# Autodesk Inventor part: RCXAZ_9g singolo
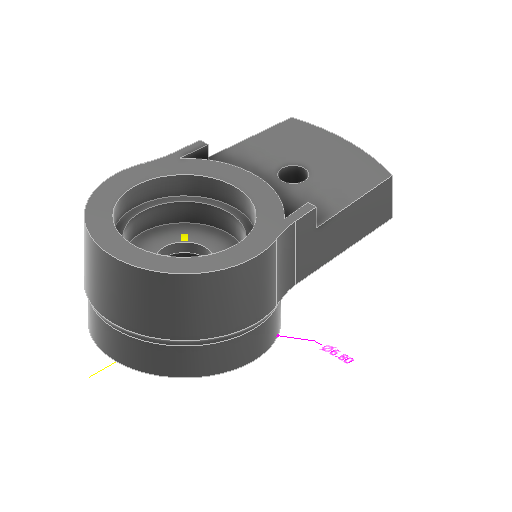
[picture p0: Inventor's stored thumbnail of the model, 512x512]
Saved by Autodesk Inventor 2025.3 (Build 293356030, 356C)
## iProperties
Created: 2026-03
Part Number: RCXAZ_9g singolo
Material: Generico
Document SubType Name: Modeling
Designer: R5800u
Density: 1 g/cm^3
Appearance: Liscia - Nero
Author: R5800u
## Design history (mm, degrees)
node "Annotazioni"
  node "Quota diametro 4" dims "d44" = 6.8 (derived)
sketch "Schizzo1"
  geometry: C1 r 3.4 at (0, 0); 1 further point
  constraints: 1 centre point, 1 coincident
  dimensions: "d0" = 6.8 diameter of C1
extrude "Estrusione1" new body sketch "Schizzo1" distance "d1" = 4; taper "d2" = 0 deg
sketch "Schizzo2" dims "d4" = 4
  geometry: L1 (0, 0)-(0, 15.5); L2 (-3.398, 0.127)-(-1.992, 15.68); L3 (0, 0)-(-8.473, 0); L4 (0, 0)-(0, -18); L5 (-3.398, -0.127)-(-3.398, 0.127); L6 (3.398, -0.127)-(3.398, 0.127); L7 (3.398, 0.127)-(1.992, 15.68); L8 (-3.386, -0.307)-(-1.767, -18.16); L9 (3.476, 0.685)-(1.767, -18.16); C1 r 3.4 at (0, 0); A1 r 3.4 centre (0, 0) between (-3.398, -0.127) and (-3.398, 0.127) reference; A2 r 1.774 centre (0, -18) between (-1.767, -18.16) and (1.767, -18.16); 11 further points
  constraints: 18 end point, 4 point on circle, 3 coincident, 3 symmetric about line, 3 tangent, 2 centre point, 2 vertical, 1 horizontal, 7 other
  dimensions: "d3" = 15.5 distance of L1.start L1.end; "d57" = 18 distance of L1.start L4.end
extrude "Estrusione2" join sketch "Schizzo2" distance "d5" = 2; taper "d6" = 0 deg
sketch "Schizzo3"
  geometry: C1 r 2.75 at (0, 0); A1 r 3.4 centre (0, 0) between (3.365, 0.485) and (-3.365, 0.485) reference; A2 r 3.4 centre (0, 0) between (3.365, 0.485) and (-3.365, 0.485) reference; A3 r 3.4 centre (0, 0) between (-3.365, 0.485) and (3.365, 0.485); 10 further points
  constraints: 2 centre point, 2 coincident, 1 point on circle
  dimensions: "d7" = 5.5 diameter of C1
extrude "Estrusione3" join sketch "Schizzo3" distance "d8" = 0.01; taper "d9" = 0 deg
sketch "Schizzo5"
  geometry: C1 r 2.75 at (0, 0) reference; 2 further points
  constraints: 1 coincident
hole "Foro1" sketch "Schizzo5" at (0, 0) diameter "d10" = 2.2; stored, may be unused: countersink angle "d14" = 90 deg, drill point angle "d16" = 118 deg; dims "d11" = 6, "d12" = 4.75, "d13" = 1, "d15" = 8
sketch "Schizzo6"
  geometry: C1 r 2.5 at (0, 0); 1 further point
  constraints: 1 centre point, 1 coincident
  dimensions: "d17" = 5 diameter of C1
extrude "Estrusione4" cut sketch "Schizzo6" distance "d18" = 2.5; taper "d19" = 0 deg
sketch "Schizzo7"
  geometry: L1 (-3.386, -0.309)-(-2, -15.5) reference; L2 (1.992, -15.681)-(3.386, -0.307) reference; A1 r 3.4 centre (0, 0) between (-3.386, -0.309) and (3.386, -0.307) reference; A2 r 2 centre (0, -15.5) between (-2, -15.5) and (1.992, -15.681) reference; 2 further points
  constraints: 1 coincident
hole "Foro2" sketch "Schizzo7" at (0, -15.5) diameter "d20" = 1.2; stored, may be unused: countersink angle "d24" = 90 deg, drill point angle "d26" = 118 deg; dims "d21" = 6, "d22" = 4.4, "d23" = 2.3, "d25" = 8
pattern_linear "Serie rettangolare1" dims "d29" = 2.4
mirror "Speculare1"
sketch "Schizzo8"
  geometry: 1 further point
sketch "Schizzo9"
  geometry: C1 r 2.375 at (0, 0) reference; C2 r 8.868 at (0, 0); C3 r 1.1 at (0, 0) reference; C4 r 25.415 at (0, 0); 1 further point
  constraints: 2 centre point, 2 coincident
extrude "Estrusione5" cut sketch "Schizzo9" extent not by distance; stored distance "d32" = 0; taper "d33" = 0 deg
sketch "Schizzo10"
  geometry: L1 (0, 0)-(9, 0); L2 (0.028, 1.9)-(9.028, 1.9); L3 (9.028, 1.9)-(9.028, -1.9); L4 (9.028, -1.9)-(0.028, -1.9); L5 (0.028, -1.9)-(0.028, 1.9); C1 r 3.4 at (0, 0) reference; 2 further points
  constraints: 10 end point, 2 horizontal, 2 parallel, 1 perpendicular, 1 other
  dimensions: "d46" = 3.8 distance of L2.end L3.end; "d69" = 9 distance of L3.end L4.end
extrude "Estrusione6" join sketch "Schizzo10" stored distance "d47" = 4; taper "d48" = 0 deg
fillet "Raccordo1" dims "d49" = 1.9
sketch "Schizzo11"
  geometry: A1 r 1.9 centre (7.128, 0) between (7.128, -1.9) and (7.128, 1.9) reference; 2 further points
  constraints: 1 coincident
hole "Foro3" sketch "Schizzo11" at (7.128, 0) diameter "d50" = 1.2; stored, may be unused: countersink angle "d54" = 90 deg, drill point angle "d56" = 118 deg; dims "d51" = 6, "d52" = 4, "d53" = 2, "d55" = 8
mirror "Speculare2"
sketch "Schizzo12"
  geometry: 1 further point
sketch "Schizzo13"
  geometry: L1 (-7.128, 1.9)-(-3.237, 1.9) reference; L2 (-3.242, -1.9)-(-7.128, -1.9) reference; L3 (-3.242, -1.9)-(-2.646, -8.464) reference; L4 (2.646, -8.464)-(3.242, -1.9) reference; L5 (3.242, -1.9)-(7.128, -1.9) reference; L6 (7.128, 1.9)-(3.237, 1.9) reference; L7 (3.237, 1.9)-(2.644, 8.465) reference; L8 (-2.644, 8.465)-(-3.237, 1.9) reference; L9 (-7.128, 2)-(-3.329, 2); L10 (-3.329, 2)-(-2.738, 8.54); L11 (2.738, 8.54)-(3.329, 2); L12 (3.329, 2)-(7.128, 2); L13 (7.128, -2)-(3.333, -2); L14 (3.333, -2)-(2.74, -8.539); L15 (-2.74, -8.539)-(-3.333, -2); L16 (-3.333, -2)-(-7.128, -2); L17 (3.945, -4.75)-(-3.945, -4.75); L18 (-3.945, -4.75)-(-3.945, 4.75); L19 (-3.945, 4.75)-(3.945, 4.75); L20 (3.945, 4.75)-(3.945, -4.75); L21 (3.945, -4.75)-(-3.945, 4.75); L22 (-3.945, -4.75)-(3.945, 4.75); C1 r 3.85 at (0, 0); C2 r 3.4 at (0, 0) reference; C3 r 0.6 at (-7.128, 0) reference; C4 r 0.6 at (0, 5.9) reference; C5 r 0.6 at (0, -5.9) reference; C6 r 0.6 at (7.128, 0) reference; A1 r 1.1 centre (0, 0) between (-1.1, 0) and (1.1, 0) reference; A2 r 0.6 centre (0, 8.3) between (-0.2, 8.866) and (0.2, 8.866) reference; A3 r 0.6 centre (0, -8.3) between (0.2, -8.866) and (-0.2, -8.866) reference; A4 r 1.9 centre (-7.128, 0) between (-7.128, 1.9) and (-7.128, -1.9) reference; A5 r 8.868 centre (0, 0) between (-2.646, -8.464) and (-0.2, -8.866) reference; A6 r 1.9 centre (7.128, 0) between (7.128, -1.9) and (7.128, 1.9) reference; A7 r 8.868 centre (0, 0) between (0.2, -8.866) and (2.646, -8.464) reference; A8 r 2 centre (-7.128, 0) between (-7.128, 2) and (-7.128, -2); A9 r 8.968 centre (0, 0) between (2.738, 8.54) and (-2.738, 8.54); A10 r 2 centre (7.128, 0) between (7.128, -2) and (7.128, 2); A11 r 8.968 centre (0, 0) between (-2.74, -8.539) and (2.74, -8.539); A12 r 2.75 centre (0, 0) between (-2.75, 0) and (2.75, 0) reference; A13 r 2.75 centre (0, 0) between (2.75, 0) and (-2.75, 0) reference; A14 r 8.868 centre (0, 0) between (2.644, 8.465) and (0.2, 8.866) reference; A15 r 8.868 centre (0, 0) between (-0.2, 8.866) and (-2.644, 8.465) reference; 16 further points
  constraints: 28 end point, 8 point on circle, 5 centre point, 2 coincident, 2 midpoint, 2 parallel, 1 horizontal, 1 horizontal alignment, 1 perpendicular, 13 other
  dimensions: "d58" = 7.7 diameter of C1; "d59" = 0.1 radial gap between concentric circles of A4 A8; "d64" = 9.5 distance of L17.end L18.end
  node "Linea chiusa proiettata2"
extrude "Estrusione7" join sketch "Schizzo13" stored distance "d60" = 10; taper "d61" = 0 deg
extrude "Estrusione8" join sketch "Schizzo13" distance "d62" = 1; taper "d63" = 0 deg
sketch "Schizzo14"
  geometry: L1 (-7.128, -2)-(-3.333, -2) reference; L2 (-3.333, -2)-(-2.74, -8.539) reference; L3 (2.74, -8.539)-(3.333, -2) reference; L4 (3.333, -2)-(7.128, -2) reference; L5 (7.128, 2)-(3.329, 2) reference; L6 (3.329, 2)-(2.738, 8.54) reference; L7 (-2.738, 8.54)-(-3.329, 2) reference; L8 (-3.329, 2)-(-7.128, 2) reference; L9 (-2.335, -8.21)-(-2.938, -1.567); L10 (-2.938, -1.567)-(-7.128, -1.567); L11 (-7.128, 1.567)-(-2.933, 1.567); L12 (-2.933, 1.567)-(-2.333, 8.21); L13 (2.333, 8.21)-(2.933, 1.567); L14 (2.933, 1.567)-(7.128, 1.567); L15 (7.128, -1.567)-(2.938, -1.567); L16 (2.938, -1.567)-(2.335, -8.21); L17 (-3.152, -4)-(3.152, -4); L18 (-3.148, 4)-(3.148, 4); L19 (-3.329, 2)-(-3.329, 1.934); L20 (-3.333, -2)-(-3.333, -1.927); L21 (3.333, -2)-(3.333, -1.927); L22 (3.329, 2)-(3.333, 1.927); C1 r 0.6 at (-7.128, 0) reference; C2 r 0.6 at (0, 5.9) reference; C3 r 0.6 at (0, -5.9) reference; C4 r 0.6 at (7.128, 0) reference; A1 r 3.85 centre (0, 0) between (-3.329, 1.934) and (-3.333, -1.927) reference; A2 r 2 centre (-7.128, 0) between (-7.128, 2) and (-7.128, -2) reference; A3 r 8.968 centre (0, 0) between (-2.74, -8.539) and (2.74, -8.539) reference; A4 r 2 centre (7.128, 0) between (7.128, -2) and (7.128, 2) reference; A5 r 8.968 centre (0, 0) between (2.738, 8.54) and (-2.738, 8.54) reference; A6 r 1.567 centre (-7.128, 0) between (-7.128, 1.567) and (-7.128, -1.567); A7 r 8.535 centre (0, 0) between (2.333, 8.21) and (-2.333, 8.21); A8 r 1.567 centre (7.128, 0) between (7.128, -1.567) and (7.128, 1.567); A9 r 8.535 centre (0, 0) between (-2.335, -8.21) and (2.335, -8.21); 9 further points
  constraints: 28 end point, 12 point on circle, 5 point on line, 4 centre point, 2 parallel, 2 vertical, 1 horizontal, 11 other
  dimensions: "d65" = 4 distance from line of point (0, 0) L18; "d66" = 4 distance from line of point (0, 0) L17
extrude "Estrusione9" join sketch "Schizzo14" stored distance "d67" = 0.4; taper "d68" = 0 deg
sketch "Schizzo15"
  geometry: L1 (-3.333, -2)-(-3.333, -1.927) reference; L2 (-3.329, 1.934)-(-3.329, 2) reference; L3 (-3.329, 2)-(-7.128, 2) reference; L4 (-7.128, -2)-(-3.333, -2) reference; L5 (-2.717, -4)-(-3.152, -4) reference; L6 (-3.152, -4)-(-2.74, -8.539) reference; L7 (2.74, -8.539)-(3.152, -4) reference; L8 (3.152, -4)-(2.717, -4) reference; L9 (2.717, -4)-(2.845, -2.594) reference; L10 (-2.845, -2.594)-(-2.717, -4) reference; L11 (3.333, 1.927)-(3.329, 2) reference; L12 (3.329, 2)-(3.148, 4) reference; L13 (3.148, 4)-(2.714, 4) reference; L14 (2.714, 4)-(2.84, 2.599) reference; L15 (-2.84, 2.599)-(-2.714, 4) reference; L16 (-2.714, 4)-(-3.148, 4) reference; L17 (-3.148, 4)-(-3.329, 2) reference; L18 (-3.329, 2)-(-3.329, 1.934) reference; L19 (-3.333, -1.927)-(-3.333, -2) reference; L20 (-3.333, -2)-(-3.152, -4) reference; L21 (-3.152, -4)-(-2.717, -4) reference; L22 (-2.717, -4)-(-2.845, -2.594) reference; L23 (2.845, -2.594)-(2.717, -4) reference; L24 (2.717, -4)-(3.152, -4) reference; L25 (3.152, -4)-(3.333, -2) reference; L26 (3.333, -2)-(3.333, -1.927) reference; L27 (3.329, 2)-(3.333, 1.927) reference; L28 (3.333, -1.927)-(3.333, -2) reference; L29 (3.333, -2)-(7.128, -2) reference; L30 (7.128, 2)-(3.329, 2) reference; C1 r 0.6 at (-7.128, 0) reference; C2 r 0.6 at (0, -5.9) reference; C3 r 2.75 at (0, 0) reference; C4 r 0.6 at (7.128, 0) reference; A1 r 3.85 centre (0, 0) between (-3.329, 1.934) and (-3.333, -1.927) reference; A2 r 2 centre (-7.128, 0) between (-7.128, 2) and (-7.128, -2) reference; A3 r 8.968 centre (0, 0) between (-2.74, -8.539) and (2.74, -8.539) reference; A4 r 3.85 centre (0, 0) between (-2.845, -2.594) and (2.845, -2.594) reference; A5 r 1.1 centre (0, 0) between (-1.1, 0) and (-1.1, 0) reference; A6 r 3.85 centre (0, 0) between (3.333, -1.927) and (3.333, 1.927) reference; A7 r 3.85 centre (0, 0) between (2.84, 2.599) and (-2.84, 2.599) reference; A8 r 3.85 centre (0, 0) between (-3.329, 1.934) and (-3.333, -1.927) reference; A9 r 3.85 centre (0, 0) between (-2.845, -2.594) and (2.845, -2.594) reference; A10 r 3.85 centre (0, 0) between (3.333, -1.927) and (3.333, 1.927) reference; A11 r 2 centre (7.128, 0) between (7.128, -2) and (7.128, 2) reference; 11 further points
  constraints: 1 coincident, 3 other
extrude "Estrusione10" cut sketch "Schizzo15" distance "d70" = 10; taper "d72" = 0 deg; dims "d71" = 5, "d73" = 0
sketch "Schizzo16"
  geometry: C1 r 3.7 at (0, 0); C2 r 3.4 at (0, 0) reference; 1 further point
  constraints: 1 centre point, 1 coincident
  dimensions: "d75" = 7.4 diameter of C1
extrude "Estrusione11" join sketch "Schizzo16" stored distance "d76" = 2; taper "d77" = 0 deg
fillet "Raccordo3" dims "d78" = 0.5
fillet "Raccordo4" dims "d79" = 5
node "Solido1"
node "Linea chiusa proiettata1"
node "Linea chiusa proiettata3"
node "Linea chiusa proiettata4"
node "Linea chiusa proiettata5"
node "Linea chiusa proiettata6"
node "Linea chiusa proiettata7"
other parameters: "d43" = 57.41156 (derived)
